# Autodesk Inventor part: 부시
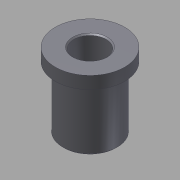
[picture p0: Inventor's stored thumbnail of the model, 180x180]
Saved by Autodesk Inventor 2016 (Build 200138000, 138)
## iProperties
Company: 한국ATC센터
Created: 2015-11
Part Number: 부시
Document SubType Name: Modeling
Designer: mdu
Density: 7.86 g/cm^3
Material: 강철, 연강
Mass: 67.5146 g
Surface Area: 43.3569 cm^2
Volume: 8.58964 cm^3
Appearance: 강철
Author: mdu
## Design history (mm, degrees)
sketch "스케치1"
  geometry: C1 r 11 at (0, 0) reference; C2 r 14 at (0, 0) reference; C3 r 11 at (0, 0) reference; 1 further point
  node "참조1"
  node "참조2"
extrude "돌출1" new body sketch "스케치1" distance "d0" = 5; taper "d1" = 0 deg
extrude "돌출2" join sketch "스케치1" distance "d2" = 25; taper "d3" = 0 deg
hole "구멍1" diameter "d6" = 13; stored, may be unused: countersink angle "d10" = 90 deg, drill point angle "d12" = 118 deg; dims "d4" = 10, "d5" = 10, "d7" = 6, "d8" = 4, "d9" = 2, "d11" = 8
chamfer "모따기1" distance "d13" = 0.5; stored, may be unused: second distance "d14" = 2, angle "d15" = 45 deg
chamfer "모따기2" distance "d16" = 0.5; stored, may be unused: second distance "d17" = 2, angle "d18" = 45 deg
node "솔리드1"
